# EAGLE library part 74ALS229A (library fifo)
FIFO
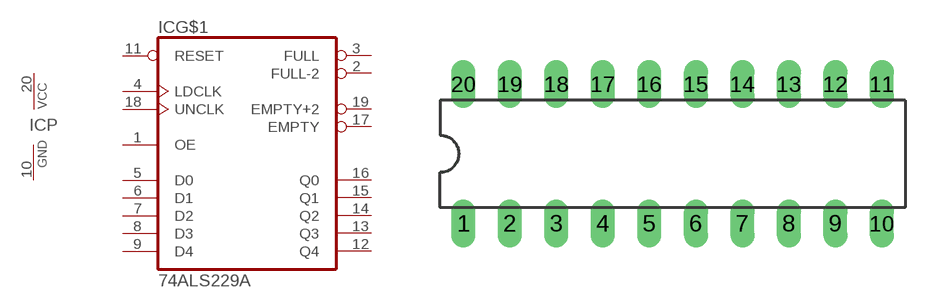
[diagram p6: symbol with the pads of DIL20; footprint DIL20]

Designator prefix IC; gates G$1=74229A P=PWRN

## 74ALS229A (OC_FARNELL: unknown; OC_NEWARK: unknown)  [DIL20]
1  G$1:OE  in
2  G$1:FULL-2  out
3  G$1:FULL  out
4  G$1:LDCLK  in
5  G$1:D0  in
6  G$1:D1  in
7  G$1:D2  in
8  G$1:D3  in
9  G$1:D4  in
10  P:GND  pwr
11  G$1:RESET  in
12  G$1:Q4  hiz
13  G$1:Q3  hiz
14  G$1:Q2  hiz
15  G$1:Q1  hiz
16  G$1:Q0  hiz
17  G$1:EMPTY  out
18  G$1:UNCLK  in
19  G$1:EMPTY+2  out
20  P:VCC  pwr

## Footprint DIL20 (pad centres in mm)
Dual In Line Package
drill 0.813 long: 1 -11.43,-3.81; 2 -8.89,-3.81; 3 -6.35,-3.81; 4 -3.81,-3.81; 5 -1.27,-3.81; 6 1.27,-3.81; 7 3.81,-3.81; 8 6.35,-3.81; 9 8.89,-3.81; 10 11.43,-3.81; 11 11.43,3.81; 12 8.89,3.81; 13 6.35,3.81; 14 3.81,3.81; 15 1.27,3.81; 16 -1.27,3.81; 17 -3.81,3.81; 18 -6.35,3.81; 19 -8.89,3.81; 20 -11.43,3.81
